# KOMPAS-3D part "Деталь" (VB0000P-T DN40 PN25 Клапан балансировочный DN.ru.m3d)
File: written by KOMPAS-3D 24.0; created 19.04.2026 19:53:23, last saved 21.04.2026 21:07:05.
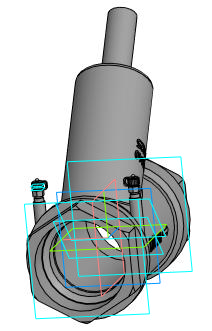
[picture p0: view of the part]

Document properties: Автор: mrdid; Полное имя файла: C:\Работа\VB0000P-T DN X PN 25 Клапан балансировочный DN.ru\DN40\исходные материалы\VB0000P-T DN40 PN25 Клапан балансировочный DN.ru.m3d

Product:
- Body: Тело 1  | qty 1
    Масса: 1.855723
- Body: Тело 2  | qty 1
    Масса: 1.855723
- Body: Тело 3  | qty 1
    Масса: 1.855723
- Body: Тело 4  | qty 1
    Масса: 1.855723
- Body: Тело 5  | qty 1
    Масса: 1.855723
- Body: Тело 6  | qty 1
    Масса: 1.855723
- Body: Тело 7  | qty 1
    Масса: 1.855723
- Body: Тело 8  | qty 1
    Масса: 1.855723
- Part/product: Деталь
    Масса: 0.00084
    Раздел спецификации: Прочие изделия
    Примечание: D080-01177

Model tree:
1. Эскиз:1
2. Элемент вращения:1
     Угол 1 = 360
3. Фаска:1  (with: Ребро.Элемент вращения:1)
     Угол = 45; Длина 1 = 3; Длина 2 = 3
4. Фаска:2  (with: Ребро.Элемент вращения:1)
     Угол = 45; Длина 1 = 2; Длина 2 = 2
5. Фаска:3  (with: Ребро.Элемент вращения:1)
     Угол = 45; Длина 1 = 1; Длина 2 = 1
6. Фаска:4  (with: Ребро.Элемент вращения:1)
     Угол = 30; Длина 1 = 4; Длина 2 = 2.3094
7. Смещенная плоскость:1  (with: Грань.Элемент вращения:1)
     Расстояние = 15
8. Эскиз:2
9. Элемент выдавливания:1  (with: Грань.Фаска:4)
     Расстояние 1 = 66.2524
10. Эскиз:3
11. Элемент выдавливания:2  (with: Грань.Фаска:4)
12. Смещенная плоскость:2  (with: Грань.Элемент вращения:1)
     Расстояние = 15
13. Эскиз:4  (with: Ребро.Фаска:4)
14. Элемент выдавливания:3  (with: Грань.Фаска:4)
     Расстояние 2 = 66.2524
15. Эскиз:5
16. Элемент выдавливания:4  (with: Грань.Фаска:4)
     Расстояние 2 = 70.2524
17. Фаска:5  (with: Ребро.Элемент выдавливания:4)
     Угол = 45; Длина 1 = 2; Длина 2 = 2
18. Плоскость под углом:1
     Угол = 45.7
19. Смещенная плоскость:3
     Расстояние = 11
20. Касательная плоскость:1  (with: Грань.Элемент вращения:1)
21. Эскиз:6  (with: Ребро.Фаска:3)
22. Элемент выдавливания:5  (with: Грань.Элемент вращения:1)
     Расстояние 1 = 7.93745; Расстояние 2 = 70
23. Эскиз:7  (with: Грань.Элемент вращения:1)
24. Элемент выдавливания:6  (with: Грань.Элемент вращения:1)
25. Эскиз:8  (with: Грань.Элемент выдавливания:6, Ребро.Элемент выдавливания:6)
26. Элемент выдавливания:7
     Расстояние 1 = 2
27. Эскиз:9  (with: Грань.Элемент выдавливания:7, Ребро.Элемент выдавливания:7)
28. Элемент выдавливания:8
     Расстояние 1 = 1
29. Эскиз:10  (with: Грань.Элемент выдавливания:8, Ребро.Элемент выдавливания:6)
30. Элемент выдавливания:10
     Расстояние 1 = 3
31. Эскиз:11  (with: Грань.Элемент выдавливания:10, Ребро.Элемент выдавливания:6)
32. Элемент выдавливания:11
     Расстояние 1 = 1
33. Эскиз:12  (with: Грань.Элемент выдавливания:11, Ребро.Элемент выдавливания:6)
34. Элемент выдавливания:12
     Расстояние 1 = 3
35. Эскиз:13  (with: Грань.Элемент выдавливания:12, Ребро.Элемент выдавливания:7)
36. Элемент выдавливания:13
     Расстояние 1 = 2
37. Скругление:1  (with: Ребро.Элемент выдавливания:13)
     Радиус = 1
38. Средняя плоскость:2  (with: Грань.Элемент выдавливания:12, Грань.Элемент выдавливания:10)
39. Эскиз:14  (with: Ребро.Элемент выдавливания:7)
40. Элемент выдавливания:14
     Расстояние 1 = 0.5
41. Средняя плоскость:3  (with: Грань.Элемент выдавливания:12)
42. Эскиз:15  (with: Вершина.Элемент выдавливания:14, Ребро.Элемент выдавливания:14)
43. Эскиз:16  (with: Грань.Элемент выдавливания:12, Ребро.Элемент выдавливания:7)
44. Элемент выдавливания:15
     Расстояние 1 = 0.5
45. Элемент выдавливания:16  (with: Грань.Элемент выдавливания:15, Грань.Элемент выдавливания:14)
     Расстояние 1 = 1.5; Расстояние 2 = 1.75
46. Скругление:2  (with: Ребро.Элемент выдавливания:14, Ребро.Элемент выдавливания:15, Ребро.Элемент выдавливания:16)
     Радиус = 1
47. Зеркальный массив:1
48. Экземпляр ( 1 )
49. Экземпляр ( 2 )  (with: Элемент выдавливания:15, Элемент выдавливания:16, Элемент выдавливания:14, Скругление:2)
50. Скругление:3  (with: Ребро.Элемент выдавливания:5)
     Радиус = 2
51. Скругление:4  (with: Ребро.Элемент выдавливания:6)
     Радиус = 1
52. Эскиз:17  (with: Грань.Элемент выдавливания:5, Ребро.Элемент выдавливания:5)
53. Элемент выдавливания:17
     Расстояние 1 = 41
54. Скругление:5  (with: Ребро.Элемент выдавливания:17, Ребро.Элемент выдавливания:5)
     Радиус = 2
55. Скругление:6  (with: Ребро.Элемент выдавливания:2, Ребро.Элемент выдавливания:4)
     Радиус = 1
56. Эскиз:19  (with: Грань.Элемент выдавливания:5)
57. Элемент выдавливания:19  (with: Грань.Элемент выдавливания:5)
     Расстояние 1 = 20.1835; Смещение 1 = 0.2
58. Эскиз:20
59. Элемент выдавливания:20  (with: Грань.Элемент вращения:1)
     Расстояние 1 = 28.2; Смещение 1 = 0.2; Расстояние 2 = 28.2; Смещение 2 = 0.2
60. Эскиз:21
61. Элемент выдавливания:21  (with: Грань.Элемент вращения:1)
     Расстояние 1 = 28.1984; Смещение 1 = 0.2
62. Эскиз:22  (with: Ребро.Фаска:2)
63. Элемент выдавливания:22
     Расстояние 1 = 62; Расстояние 2 = 78.1355

Expressions: 1/2*25.4
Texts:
  Линейный размер с обрывом
  GOST 26.020 Pr3
  var3D
  Dn+1
  Ds-1
  Ds-2
  Ds-4
  Gn+S+5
